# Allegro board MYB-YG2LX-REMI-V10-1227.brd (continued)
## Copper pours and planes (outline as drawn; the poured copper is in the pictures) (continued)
VDD_3V3 on BOTTOM: 26.31,48.72 26.31,47.8 25.8,47.29 24.61,47.29 24.46,47.45 24.46,48.26 24.51,48.31 25.14,48.31 25.22,48.39 25.22,48.87 25.35,49 26.03,49
VDD_3V3 on BOTTOM: 54.45,16.13 55.72,16.13 56.08,15.77 56.08,15.01 55.95,14.88 55.14,14.88 55.01,14.76 54.07,14.76 53.95,14.88 53.95,15.6 54.3,15.95 54.3,15.98
VDD_3V3 on ART04: 28.83,32.94 29.99,32.94 30.2,32.74 30.2,31.95 30.07,31.83 29.03,31.83 28.77,32.08 28.77,32.89
VDD_3V3 on ART04: 10.36,60.35 11.43,60.35 12.47,61.39 12.47,63.86 14.35,65.74 15.46,65.74 18.16,68.43 38.58,68.43 40.18,66.83 40.18,61.7 38.15,59.66 29.94,59.66 26.54,63.07 16.38,63.07 15.64,62.33 15.64,59.05 15.31,58.72 10.36,58.72 10.26,58.83 10.26,60.25
VDD_3V3 on POW05: 15.09,4.42 14.55,4.96 14.55,11.38 13.87,12.06 12.08,12.06 11.07,11.05 11.07,8.06 10.58,7.57 8.46,7.57 7.57,8.46 7.57,62.28 8.15,62.87 10.26,62.87 10.29,62.89 10.94,62.89 11.63,62.2 11.63,46.33 10.03,44.73 10.03,40.48 10.81,39.7 11.91,39.7 14.68,36.93 14.68,20.45 11.98,17.76 11.98,13.92 12.67,13.23 15.94,13.23 17.17,12.01 17.17,8.39 16.35,7.57 16.35,6.3 17.11,5.54 25.07,5.54 25.07,5.19 24.3,4.42
VDD_3V3 on POW05: 95.99,2.54 96.34,2.89 96.34,7.88 94.97,9.25 92.81,9.25 92.38,9.68 92.38,11.66 91.44,12.6 88.82,12.6 86.94,14.48 46.84,14.48 45.64,15.67 33.88,15.67 32.11,17.45 31.47,17.45 31.09,17.83 31.09,31.27 30.51,31.85 29.21,31.85 28.98,32.08 28.98,37.44 29.72,38.18 31.65,38.18 33.24,39.77 33.24,46.26 32.38,47.12 24.61,47.12 24.2,47.53 24.2,58.54 25.07,59.41 37.54,59.41 39.04,60.91 39.04,63.57 39.62,64.16 74.64,64.16 80.82,57.99 99.31,57.99 100.2,57.1 100.2,50.73 98.27,48.8 98.27,34.92 102.61,30.58 102.61,10.61 106.19,7.04 109.97,7.04 110,7.01 116.75,7.01 117.88,5.89 117.88,2.67 117.75,2.54
VDD_5V on TOP: 9.62,43.54 13.05,43.54 13.05,40.39 12.8,40.13 10.84,40.13 10.44,40.54 10.44,41.78 9.55,42.67 9.55,43.46
VDD_5V on TOP: 29.26,16.87 32.05,16.87 32.08,16.84 32.08,8.15 29.82,8.15 29.74,8.23 29.74,11.28 27.25,13.77 25.4,13.77 25.32,13.84 25.32,15.34 25.78,15.8 28.19,15.8
VDD_5V on TOP: 39.09,35.64 39.62,35.64 39.9,35.36 39.9,32.11 39.54,31.75 37.94,31.75 37.78,31.92 37.78,33.08 37.64,33.22 37.64,33.93 37.09,34.48 37.09,38.37 36.6,38.86 35.73,38.86 35.45,39.14 35.45,40.69 35.71,40.94 38.17,40.94 38.86,40.26 38.86,35.86
VDD_5V on TOP: 100.68,48.34 102.59,48.34 102.79,48.13 102.79,45.9 102.59,45.69 100.94,45.69 100.5,46.13 100.5,48.16
VDD_5V on TOP: 31.39,40.61 33.35,40.61 33.73,41 33.73,42.8 34.77,42.8 34.77,41.22 35.05,40.94 37,40.94 37.41,40.54 37.41,39.5 36.78,38.86 31.57,38.86 31.37,38.66 30.02,38.66 29.64,39.04 29.64,40.11 29.87,40.34 31.11,40.34
VDD_5V on TOP: 10.82,17.35 12.54,17.35 12.85,17.65 12.85,18.01 13.25,18.41 15.11,18.41 15.25,18.28 15.25,16.5 15.01,16.26 12.65,16.26 12.45,16.45 10.83,16.45 10.77,16.51 10.77,17.3
VDD_5V on TOP: 94.1,50.16 96.01,50.16 96.24,49.94 96.24,47.83 96.11,47.7 94.2,47.7 93.9,48.01 93.9,49.96
VDD_5V on TOP: 39.59,68.61 40.36,68.61 40.59,68.38 41.6,68.38 41.83,68.61 43.25,68.61 43.35,68.5 43.35,65.71 43.07,65.43 39.65,65.43 39.42,65.66 39.42,68.43
VDD_5V on BOTTOM: 76.27,14.66 77.01,14.66 77.36,14.3 77.36,11.56 77.03,11.23 77.01,11.23 77.01,10.06 77.09,9.98 77.09,8.66 77.01,8.59 76.2,8.59 76.02,8.76 76.02,14.4
VDD_5V on BOTTOM: 39.98,67.54 42.52,67.54 42.77,67.28 42.77,66.19 42.52,65.94 39.98,65.94 39.82,66.09 39.82,67.39
VDD_5V on BOTTOM: 102.59,48.34 102.79,48.13 102.79,45.9 102.59,45.69 100.91,45.69 100.9,45.71 100.03,45.71 99.64,46.1 99.64,47.73 100.25,48.34
VDD_5V on BOTTOM: 94.41,49.35 97.07,49.35 97.25,49.17 97.25,47.88 97.07,47.7 94.36,47.7 94.08,47.98 94.08,49.02
VDD_5V on BOTTOM: 40.28,5.97 39.7,6.55 30.04,6.55 29.8,6.8 29.8,11.17 30.15,11.52 41.03,11.52 43.3,9.25 48,9.25 49.39,10.63 53.65,10.63 54.1,10.19 54.1,8.84 54.35,8.59 56.64,8.59 57.63,7.59 57.63,5.49 57.15,5 53.01,5 52.04,5.97
VDD_5V on BOTTOM: 95.35,3.68 95.35,2.69 95.27,2.62 93.81,2.62 93.68,2.74 93.68,3.92 93.82,4.06 94.97,4.06
VDD_5V on BOTTOM: 44.19,58.32 44.19,56.59 43.28,55.68 39.32,55.68 38.32,56.67 38.32,57.48 36.06,59.74 31.75,59.74 31.44,60.05 21.23,60.05 20.25,59.07 16.21,59.07 15.92,59.36 15.92,62.99 15.95,63.02 15.95,66.88 18.16,69.09 37.26,69.09 38.81,67.54 38.81,61.54 40.26,60.1 43.96,60.1 44.4,59.66 44.4,58.52
VDD_5V on ART04: 16.53,62.66 25.65,62.66 26.49,61.82 26.49,59.44 25.24,58.19 25.24,49.76 22.95,47.46 22.95,44.13 21.61,42.8 19.68,42.8 14.54,37.66 14.54,24.18 16.75,21.97 22.37,21.97 26.73,17.61 28.41,17.61 28.83,17.2 32.64,17.2 32.64,14.53 32.03,13.92 32.03,9.53 31.87,9.37 29.94,9.37 29.84,9.47 29.84,10.9 28.67,12.06 26.06,12.06 25.88,11.89 14.17,11.89 13.97,12.09 11.73,12.09 11.53,11.89 8.33,11.89 8,12.22 8,49.33 8.91,50.24 17.62,50.24 20.54,53.16 20.54,57.76 19.38,58.93 15.92,58.93 15.92,62.05
VDD_5V on ART04: 93.14,2.62 97.68,2.62 105.08,10.01 105.08,42.16 105.41,42.49 105.41,46.13 103.27,48.26 101.7,48.26 100.83,49.12 95.78,49.12 95.17,48.51 95.17,47.35 96.31,46.2 101.77,46.2 102.99,44.98 102.99,12.17 95.37,4.55 93.04,4.55 93.04,2.72
VDD_5V on POW05: 87.43,2.54 86.71,3.25 86.71,6.94 84.94,8.71 70.79,8.71 70.77,8.74 69.66,8.74 69.64,8.71 29.84,8.71 29.75,8.8 29.75,10.93 28.62,12.06 26.58,12.06 25.07,10.55 25.07,6.05 17.32,6.05 16.86,6.51 16.86,7.36 17.67,8.18 17.67,12.22 16.15,13.74 12.88,13.74 12.49,14.13 12.49,17.55 15.19,20.24 15.19,37.14 12.12,40.21 11.02,40.21 10.54,40.69 10.54,44.52 12.14,46.12 12.14,62.41 11.15,63.4 10.8,63.4 12.14,64.74 12.14,66.27 14.3,68.43 29.1,68.43 29.66,68.99 38.93,68.99 39.49,68.43 42.44,68.43 42.44,64.8 42.31,64.67 39.41,64.67 38.53,63.78 38.53,61.12 37.33,59.92 24.86,59.92 23.69,58.75 23.69,47.32 24.4,46.61 32.17,46.61 32.74,46.05 32.74,39.98 31.44,38.68 29.51,38.68 28.47,37.65 28.47,31.87 29,31.34 30.29,31.34 30.58,31.06 30.58,17.62 31.26,16.94 31.9,16.94 33.67,15.16 45.43,15.16 46.63,13.97 86.73,13.97 88.61,12.09 91.23,12.09 91.87,11.45 91.87,9.47 92.6,8.74 94.76,8.74 95.83,7.67 95.83,3.1 95.27,2.54
VDD_5V_VBUS on TOP: 105.05,52.58 113.23,52.58 113.64,52.17 113.64,50.88 108.66,50.88 106.98,49.2 106.98,46.58 106.9,46.51 104.9,46.51 104.75,46.66 104.75,52.27
VDD_5V_VBUS on BOTTOM: 104.82,52.58 113.36,52.58 113.94,51.99 113.94,51.05 113.76,50.88 108.66,50.88 108.33,50.55 108.3,50.55 107.01,49.25 107.01,46.51 106.8,46.3 105.33,46.3 104.8,46.84 104.8,52.55
VDD_5V_VBUS on ART04: 94.66,52.6 113.41,52.6 113.69,52.32 113.69,50.88 108.43,50.88 107.9,50.34 107.87,50.34 106.93,49.4 106.93,48.87 106.8,48.74 101.8,48.74 101.44,49.1 101.42,49.1 100.96,49.56 94.89,49.56 94.31,50.14 94.31,52.25
VDD_BAT on BOTTOM: 69.8,65.43 70.86,65.43 70.94,65.35 70.94,63.64 70.81,63.51 69.78,63.51 69.59,63.7 69.59,65.23
VDD_BL_3V3 on BOTTOM: 26.79,49.05 27.78,49.05 28.6,48.23 28.6,46.02 28.83,45.8 28.83,44.73 28.11,44.02 25.8,44.02 25.49,44.34 25.49,45.12 25.95,45.59 26.64,45.59 26.74,45.69 26.74,49
VDD_BL_3V3 on ART04: 29.13,53.42 29.63,52.92 29.63,41.97 28.49,40.84 25.6,40.84 25.14,40.39 25.14,38.66 24.86,38.38 19.63,38.38 19.05,38.96 19.05,41.66 19.88,42.49 21.92,42.49 23.26,43.84 23.26,47.35 25.57,49.66 25.57,53.31 25.68,53.42
VDD_LDO on TOP: 67.66,10.69 70.94,10.69 71.01,10.62 71.01,10.13 70.99,10.11 69.11,10.11 68.96,10.26 68.09,10.26 67.94,10.11 67.59,10.11 67.59,10.62
VDD_LDO on TOP: 71.09,11.79 67.76,11.79 67.71,11.84 67.71,12.47 68.3,13.06 71.22,13.06 71.29,12.98 71.29,11.99
VDD_PHY0_3V3 on TOP: 101.22,22.66 102.87,22.66 103.12,22.4 103.12,21.56 102.76,21.21 101.24,21.21 101.09,21.36 101.09,22.53
VDD_PHY0_3V3 on TOP: 90.29,18.14 92.12,18.14 92.2,18.06 92.2,17.55 92.12,17.48 90.27,17.48 90.24,17.5 90.24,18.08
VDD_PHY0_3V3 on BOTTOM: 101.24,22.63 102.46,22.63 102.64,22.45 102.64,21.36 102.51,21.23 101.24,21.23 101.11,21.36 101.11,22.5
VDD_PHY0_3V3 on BOTTOM: 90.39,18.59 91.92,18.59 92.05,18.47 92.05,17.17 91.99,17.12 90.85,17.12 90.27,17.7 90.27,18.47
VDD_PHY0_3V3 on ART04: 96.74,24.79 96.74,26.72 97.51,27.48 102.18,27.48 102.64,27.03 102.64,21.55 102.18,21.09 100.69,21.09 100.35,21.44 100.35,22.96 99.74,23.57 99.74,24.82 99.49,25.07 98.4,25.07 97.82,24.5 97.82,22.64 94.42,19.24 94.43,19.23 94.43,17.63 94.1,17.3 90.37,17.3 90.14,17.53 90.14,18.24 90.37,18.47 91.36,18.47 91.97,19.08 91.97,22.76 94,24.79
VDD_PHY1_3V3 on TOP: 91.16,37.69 92.07,37.69 92.15,37.62 92.15,37.13 92.1,37.08 90.27,37.08 90.24,37.11 90.24,37.64 90.34,37.74 91.11,37.74
VDD_PHY1_3V3 on TOP: 95.75,29.18 97.33,29.18 97.61,28.91 97.61,27.33 97.38,27.1 95.7,27.1 95.53,27.28 95.53,28.96
VDD_PHY1_3V3 on BOTTOM: 91.18,37.57 91.18,37.36 91.39,37.16 91.79,37.16 91.92,37.03 91.92,36.55 91.84,36.47 91.33,36.47 90.75,37.06 90.34,37.06 90.29,37.11 90.29,37.54 90.47,37.72 91.03,37.72
VDD_PHY1_3V3 on ART04: 91.79,37.87 92.78,37.87 92.86,37.8 92.86,37.31 92.63,37.08 90.29,37.08 90.22,37.16 90.22,37.59 90.34,37.72 91.64,37.72
VDD_RGMII0 on BOTTOM: 92.07,19.91 92.68,20.52 93.37,20.52 93.47,20.42 93.47,19.28 93.19,19 92.33,19 92.22,18.9 89.66,18.9 89.56,19 89.56,19.76 89.71,19.91
VDD_RGMII0 on ART04: 89.58,28.7 91.13,27.15 91.13,19.43 90.57,18.87 89.45,18.87 87.66,20.66 86.78,20.66 86.28,21.16 86.28,28.45 86.53,28.7
VDD_RGMII1 on BOTTOM: 90.62,38.38 91.26,38.38 91.61,38.02 93.06,38.02 93.25,37.83 93.25,36.25 93.51,35.99 93.51,33.85 93.16,33.5 90.55,33.5 90.45,33.6 90.45,34.54 90.65,34.75 92.2,34.75 92.35,34.9 92.35,37.13 92.15,37.34 91.56,37.34 91.28,37.62 91.28,37.77 91.18,37.87 90.6,37.87 90.52,37.95 90.52,38.28
VDD_RGMII1 on ART04: 88.77,44.63 88.13,43.99 85.34,43.99 84.22,42.88 84.22,40.59 84.55,40.26 91.23,40.26 91.84,39.65 91.84,38.4 91.46,38.02 90.6,38.02 90.5,38.13 90.5,38.3 90.27,38.53 89.51,38.53 89.02,38.05 89.02,37.44 89.66,36.8 91.51,36.8 91.84,36.47 91.84,33.58 91.39,33.12 83.82,33.12 83.44,33.5 83.44,49.48 83.87,49.91 88.21,49.91 88.77,49.35
VDD_RTC on BOTTOM: 73.1,67.16 76.6,67.16 76.83,66.93 76.83,66.27 76.58,66.01 74.82,66.01 74.52,65.71 74.52,64.69 73.94,64.11 73.12,64.11 72.89,64.34 72.89,66.95
VDD_RTC on BOTTOM: 68.22,67.39 68.93,67.39 69.16,67.16 69.16,63.25 68.96,63.04 67.71,63.04 67.71,66.88
VDD_RTC on ART04: 69.11,69.34 73.88,69.34 74.75,68.48 74.75,64.9 74.19,64.34 67.2,64.34 67.1,64.44 67.1,67.34
VDD_SD on TOP: 7.84,61.49 8.58,61.49 8.81,61.26 8.81,59.44 8.73,59.36 7.59,59.36 7.59,61.24
VDD_SD on BOTTOM: 8.86,61.98 8.86,59.16 8.71,59 7.59,59 7.46,59.13 7.46,62.03 7.59,62.15 8.68,62.15
VDD_SD on ART04: 7.77,61.47 9.52,61.47 9.85,61.14 9.85,57.53 9.95,57.43 18.51,57.43 19,57.91 19.48,57.91 19.88,57.51 19.88,53.9 16.76,50.77 14.68,50.77 14.32,51.13 14.32,51.38 13.71,51.99 13.15,51.99 13,51.84 13,51.08 12.8,50.88 12.09,50.88 11.4,51.56 7.59,51.56 7.57,51.59 7.57,61.26
VDD_SOM_3V3OUT on TOP: 11.02,62.08 11.02,60.78 10.94,60.71 9.32,60.71 9.22,60.81 9.22,62.13 9.32,62.23 10.87,62.23
VDD_SOM_3V3OUT on ART03: 11.17,62.08 11.22,62.03 11.22,60.71 11.12,60.6 9.29,60.6 9.06,60.83 9.06,61.8 9.34,62.08
VDD_SOM_3V3OUT on ART04: 10.08,62.23 11.15,62.23 11.25,62.13 11.25,60.88 11.07,60.71 10.38,60.71 9.95,61.14 9.95,62.1
VDD_SOM_5VIN on TOP: 47.14,50.9 43.96,50.9 43.95,50.91 43.7,50.91 43.53,51.08 43.53,53.31 43.76,53.54 47.14,53.54 47.47,53.21 47.47,51.23
VDD_SOM_5VIN on BOTTOM: 47.32,51.21 47.32,54.03 47.04,54.31 47.04,57.89 46.76,58.17 45.08,58.17 44.98,58.06 44.98,55.83 44.62,55.47 44.19,55.47 44.08,55.36 44.08,53.86 43.56,53.34 43.56,51.05 43.68,50.93 47.04,50.93
VDD_USB0_VBUS on TOP: 86.94,8.56 89.53,8.56 90.55,7.54 90.55,5.69 90.42,5.56 87.73,5.56 86.76,4.6 86.76,3.38 86.48,3.1 83.97,3.1 83.66,2.79 81.78,2.79 81.76,2.82 81.76,4.11 81.96,4.11 82.06,4.22 82.06,4.5 84.71,4.5 86.58,6.38 86.58,8.2
VDD_USB0_VBUS on TOP: 79.02,7.65 79.27,7.65 79.35,7.57 79.35,6.12 79.4,6.07 81.1,6.07 81.4,6.38 81.4,7.59 81.45,7.65 81.83,7.65 81.83,6.25 81.58,5.99 81.58,5.08 82.14,4.52 82.14,2.79 78.48,2.79 78.1,3.17 78.1,4.5 78.63,5.03 78.63,6.12 78.89,6.38 78.89,7.52
VDD_USB0_VBUS on BOTTOM: 78.13,2.31 77.87,2.57 77.87,3.91 78.13,4.17 78.13,4.45 78.38,4.7 78.66,4.7 78.71,4.65 78.71,3.61 79.22,3.1 80.01,3.1 80.69,3.78 81.3,3.78 81.5,3.99 81.5,4.62 81.58,4.7 84.88,4.7 85.39,5.21 85.39,6.6 86.61,7.82 86.61,9.6 86.89,9.88 88.95,9.88 89.05,9.78 89.05,9.07 89.11,9 90.23,9 91.06,9.83 92.05,9.83 92.05,8.33 90.14,6.43 87.87,6.43 87.59,6.15 87.59,3.77 86.56,2.74 83.97,2.74 83.54,2.31
VDD_VBUS on TOP: 63.06,9.07 63.65,9.07 63.85,8.86 63.85,6.91 64.41,6.35 64.41,6.17 64.36,6.12 64,6.12 63.22,6.91 63.22,8 62.96,8.26 62.96,8.97
VDD_VBUS on TOP: 59.84,4.75 58.01,4.75 57.73,5.03 51.91,5.03 51.2,5.74 51.2,8.18 51.61,8.59 56.79,8.59 57.91,7.47 59.84,7.47
VDD_VBUS on TOP: 64.88,6.74 65.1,6.53 66.77,6.53 66.98,6.73 67.61,6.73 67.89,7.01 67.89,8.1 67.79,8.2 67.79,9.19 68.04,9.45 68.04,10.01 68.09,10.06 68.8,10.06 68.98,9.88 68.98,8.28 68.78,8.08 68.78,3.35 68.27,2.84 63.72,2.84 62.48,4.09 60.63,4.09 59.97,4.75 58.09,4.75 57.93,4.9 57.93,7.47 62.35,7.47 62.91,8.03 62.91,8.99 63.85,8.99 63.98,8.86 63.98,8.28 64,8.26 64,6.86 64.12,6.74
VDD_VBUS on TOP: 68.7,9.07 68.12,9.07 67.91,8.86 67.91,6.91 67.35,6.35 67.35,6.17 67.41,6.12 67.76,6.12 68.55,6.91 68.55,8 68.8,8.26 68.8,8.97
VDD_VBUS on BOTTOM: 60.6,4.11 60.07,4.65 58.19,4.65 57.93,4.9 57.93,7.87 59,8.94 59.79,8.94 60.04,9.19 60.91,9.19 61.16,8.94 62.76,8.94 62.81,8.99 64.41,8.99 64.87,8.53 64.87,6.76 65.1,6.53 66.77,6.53 66.9,6.65 66.9,8.64 67.23,8.97 67.51,8.97 67.51,9.07 67.79,9.35 67.79,11 67.53,11.25 66.93,11.25 66.87,11.3 66.87,11.58 66.98,11.68 68.02,11.68 68.06,11.65 68.64,11.65 68.65,11.63 69.72,11.63 70.23,11.13 70.23,9.47 69.13,8.38 69.13,4.7 67.26,2.82 63.72,2.82 62.43,4.11
VDD_VBUS on ART03: 57.76,4.8 57.35,5.21 57.35,6.99 57.81,7.44 58.59,7.44 59.1,7.95 59.1,10.79 59.41,11.1 66.32,11.1 67.28,10.13 68.86,10.13 69.16,9.83 69.16,9.07 68.78,8.69 68.78,7.26 68.09,6.58 68.09,5.64 67.97,5.51 66.06,5.51 64.61,4.06 58.52,4.06 57.78,4.8
VDD_VBUS_5V on TOP: 57.65,2.57 55.9,2.57 55.9,2.54 55.5,2.13 55.5,0.69 55.44,0.64 53.79,0.64 53.46,0.97 53.46,4.52 53.62,4.67 57.4,4.67 57.65,4.42
VDD_VBUS_5V on BOTTOM: 54.86,4.24 58.06,4.24 58.14,4.17 58.14,1.96 58.11,1.93 54.71,1.93 54.61,2.03 54.61,3.99
VDD_VBUS_5V on ART04: 33.93,18.59 33.85,18.52 31.21,18.52 30.83,18.9 30.83,21.74 31.11,22.02 33.57,22.02 33.93,21.67
VDD_VBUS_5V on ART04: 54.4,4.55 57.25,4.55 57.7,4.09 57.7,3.2 57.53,3.02 54.66,3.02 54.4,3.28
VDDA_AUDIO_3V3 on BOTTOM: 38.15,18.41 41.7,18.41 41.7,16.79 41.63,16.71 38.17,16.71 38.02,16.87 38.02,18.29
VDDA_PHY0_1V1 on BOTTOM: 99.21,24.99 99.31,24.89 99.31,24.23 99.26,24.18 97.18,24.18 97.13,24.23 97.13,24.79 97.33,24.99
VDDA_PHY0_1V1 on ART04: 98.32,24.77 99.28,24.77 99.56,24.49 99.56,21.79 99.06,21.29 98.47,21.29 98.19,21.56 98.19,24.64
VDDA_PHY0_3V3 on TOP: 100.43,13.89 101.55,13.89 101.57,13.87 101.57,12.57 101.44,12.45 100.53,12.45 100.33,12.65 100.33,13.79
VDDA_PHY1_1V1 on BOTTOM: 99.31,42.52 100.5,42.52 100.55,42.47 100.55,41.78 100.4,41.63 100.4,41.27 100.17,41.05 99.31,41.05 99.16,41.2 99.16,42.37
VDDA_PHY1_3V3 on TOP: 100.91,33.48 102.03,33.48 102.1,33.4 102.1,32.11 101.98,31.98 100.96,31.98 100.76,32.18 100.76,33.32
VDDL_PHY0_1V1 on BOTTOM: 86.84,15.06 89.63,15.06 90.04,14.66 90.93,14.66 91.06,14.53 91.06,14.22 90.95,14.12 89.35,14.12 88.87,13.64 88.87,12.42 86.84,12.42
VDDL_PHY0_1V1 on BOTTOM: 96.01,25.98 96.41,25.98 96.82,25.58 96.82,23.77 96.72,23.67 95.96,23.67 95.86,23.77 95.86,25.83
VDDL_PHY0_1V1 on ART04: 92.6,26.92 96.16,26.92 96.44,26.64 96.44,25.17 96.36,25.1 95.88,25.1 95.42,25.55 93.72,25.55 93.01,24.84 93.01,24.43 92.91,24.33 92.43,24.33 92.17,24.59 92.17,26.49
VDDL_PHY1_1V1 on TOP: 99.97,44.42 100.94,44.42 100.99,44.37 100.99,42.75 100.91,42.67 100.2,42.67 100.12,42.75 100.12,43.54 99.89,43.76 99.89,44.35
VDDL_PHY1_1V1 on BOTTOM: 100.07,44.48 100.71,44.48 101.01,44.17 101.01,42.93 100.91,42.82 99.89,42.82 99.77,42.95 99.77,44.17
VDDL_PHY1_1V1 on BOTTOM: 84.96,35.31 84.83,35.18 83.99,35.18 83.89,35.28 83.89,41.43 84.02,41.55 85.29,41.55 85.39,41.45 85.39,40.64 84.96,40.21
VDDL_PHY1_1V1 on ART04: 89.04,43.7 91.23,45.9 100.35,45.9 100.83,45.42 100.83,43.89 100.76,43.81 99.77,43.81 99.61,43.97 98.47,43.97 97.74,43.23 95.25,43.23 94.97,42.95 94.97,40.92 94.53,40.49 84.71,40.49 84.53,40.67 84.53,42.75 85.48,43.7
AUDIO_AGND on BOTTOM: 38.32,12.32 37.54,13.11 35.45,13.11 35.2,13.36 35.2,14.58 35.43,14.81 37.51,14.81 38.05,15.34 38.05,16.26 38.15,16.36 42.11,16.36 42.41,16.66 42.41,22.15 41.65,22.91 41.65,24.82 41.68,24.84 43.68,24.84 43.99,24.54 43.99,12.9 43.4,12.32
LT8912_VCCA_HDMIPLL on BOTTOM: 16.23,28.27 16.3,28.19 16.3,25.81 15.92,25.43 14.47,25.43 14.47,26.24 14.3,26.42 14.3,28.19 14.37,28.27
LT8912_VCCA_HDMIPLL on BOTTOM: 19.96,21.56 19.96,20.7 19.88,20.62 19,20.62 18.74,20.37 18.74,19.81 18.67,19.74 17.37,19.74 17.04,20.07 14.73,20.07 14.47,20.32 14.47,26.06 16.3,26.06 16.3,22 16.46,21.84 19.68,21.84
LT8912_VCCA_HDMITX on BOTTOM: 26.51,24.74 27.12,24.13 27.12,21.49 26.74,21.11 24.18,21.11 24.02,21.26 24.02,22.02 24.23,22.23 24.81,22.23 24.94,22.35 24.94,23.27 25.04,23.37 25.27,23.37 25.35,23.44 25.35,24.61 25.47,24.74
N23725979 on BOTTOM: 9.55,45.72 11.2,45.72 11.45,45.47 11.45,41.81 11.3,41.66 10.36,41.66 10.23,41.78 10.23,43 10,43.23 9.62,43.23 9.34,43.51 9.34,45.52
N24697239 on TOP: 92.17,17.17 92.17,17.07 92.1,16.99 91.54,16.99 90.93,16.38 90.19,16.38 90.17,16.41 90.17,17.02 90.39,17.25 92.1,17.25
N24697239 on BOTTOM: 87.93,17.3 90.19,17.3 90.67,16.81 91,16.81 91,16.38 90.93,16.31 89.99,16.31 89.76,16.08 87.93,16.08 87.78,16.23 87.78,17.14
N24806599 on TOP: 92.17,36.81 92.17,36.7 92.1,36.63 91.54,36.63 90.88,35.97 90.24,35.97 90.17,36.65 90.39,36.88 92.1,36.88
N24806599 on BOTTOM: 90.67,36.73 91.08,36.32 91.08,36.17 90.88,35.97 90.22,35.97 89.96,35.71 89.96,35.23 89.91,35.18 86.15,35.18 85.95,35.38 85.95,37.06 86.1,37.21 88.77,37.21 89.25,36.73
N25530830 on BOTTOM: 55.04,14.55 57.48,14.55 57.7,14.33 57.7,13.97 57.88,13.79 58.9,13.79 59.05,13.64 59.05,11.76 58.72,11.43 57.96,11.43 57.73,11.66 57.73,12.9 57.53,13.11 57.53,13.13 55.09,13.13 54.99,13.23 54.99,14.5
N25531113 on BOTTOM: 48.22,13.78 48.41,13.97 48.41,14.55 49.07,14.55 49.15,14.48 49.15,14.05 49.27,13.92 50.44,13.92 50.9,13.46 50.9,11.71 50.69,11.51 49.91,11.51 49.58,11.84 49.58,12.83 49.25,13.16 48.38,13.16 48.28,13.06 47.09,13.06 46.99,13.16 46.99,13.67 47.1,13.78
N25776699 on BOTTOM: 8.73,45.77 9.06,45.44 9.06,41.81 8.76,41.5 7.59,41.5 7.59,45.59 7.77,45.77
N26033282 on TOP: 39.72,45.11 41.6,45.11 41.96,44.75 41.96,42.11 41.3,41.45 35.12,41.45 35.07,41.5 35.07,42.93 35.28,43.13 38.71,43.13 39.42,43.84 39.42,44.81
N26043137 on TOP: 39.11,28.88 38.91,29.08 38.91,30.28 39.11,30.48 42.95,30.48 43.15,30.28 43.15,29.06 42.97,28.88
N26045371 on BOTTOM: 21.81,50.52 23.01,50.52 23.29,50.8 24.28,50.8 24.48,50.6 24.48,49.94 23.92,49.38 23.34,49.38 22.68,48.72 22.68,46.56 22.42,46.3 21.94,46.3 21.84,46.41 21.84,48.97 21.66,49.15 21.66,50.37
N26059117 on BOTTOM: 96.26,7.85 99.21,7.85 99.64,7.42 99.64,6.93 99.46,6.76 97.76,6.76 97.13,6.12 97.13,4.52 96.86,4.25 96.2,4.25 95.73,4.72 95.73,7.32
N26059441 on BOTTOM: 94.51,7.87 95.32,7.87 95.42,7.77 95.42,4.67 96.21,3.89 97.51,3.89 97.76,4.14 97.76,4.9 98.93,6.07 99.54,6.07 99.79,5.82 99.79,5.18 98.98,4.37 98.98,2.95 98.34,2.31 95.91,2.31 95.63,2.59 95.63,3.91 94.56,4.98 94.46,4.98 94.46,7.82
N26059598 on BOTTOM: 96.24,9.88 96.63,9.49 96.63,8.62 96.34,8.33 92.81,8.33 92.68,8.46 92.68,9.58 92.99,9.88
N26081452 on TOP: 32.08,32.49 33.12,32.49 33.35,32.26 33.35,30.18 33.75,29.77 35.45,29.77 35.76,29.46 35.76,29.01 35.2,28.45 32.13,28.45 32.13,29.49 31.75,29.87 31.75,31.17 32.08,31.5
N26137432 on TOP: 97.76,52.43 98.04,52.43 98.13,52.34 98.13,51.5 98.47,51.16 99.72,51.16 99.82,51.05 99.82,50.14 99.72,50.04 98.83,50.04 97.86,49.07 97.07,49.07 96.74,49.4 96.74,50.55 97.61,51.41 97.61,51.64 97.68,51.71 97.68,52.35
N26137432 on BOTTOM: 98.32,51.21 99.77,51.21 99.82,51.16 99.82,50.14 99.69,50.01 98.4,50.01 98.29,50.11 98.29,51.18

Small or netless copper shapes (teardrops, artwork), in the pictures only: 1 on TOP

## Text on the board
Ref Des/Silkscreen Bottom: J5 | eMMC | Download | Boot Device | 0 | S0 | S1 | 1 | S2 | Micro SD
User.Comments: CR_1_1 | CR_3_1
Board Geometry/Outline: ROUT
Board Geometry/Soldermask Top: Remi Pi
Ref Des/Silkscreen Top: J6 | J2 | M33 Debug | U11 | J7 | U7 | A55 Debug | U22 | Y4 | U3 | U24 | U15 | U4 | J8 | L2 | OFF/ON | U1 | U26 | J13 | J1 | J3 | J14 | S0 | S2 | S1 | ON | Y7 | 1 | U16 | SW1 | U10 | 0 | OFF | J4 | J9 | J10 | MIPI CSI | LVDS | Reset | User | USB HOST | ENET0 | ENET1 | HDMI | WL ANT | WL/BT ANT | AUDIO | VBUS_5V | USB type-c | MYB-YG2LX-REMI_V10
DIMENSION: 100 ohm | 90 ohm | 50 ohm | 1,6 | 1 | 3 | 17.0 | + | - | 5 | L2&L5 | L3 | L2 | MYB-YG2LX_V01 | 2022-10-27
User.14: FIGURE | SIZE | 8.0 | 19.69 | 23.62 | 35.43 | 36.22 | 86.61 | 125.0 | 125.98 | 127.95 | 25.59 | 39.37 | 66.93 | 70.87 | 118.11 | 47.24x23.62 | 59.06x27.56 | 62.99x23.62 | 62.99x39.37 | 70.87x23.62 | 70.87x27.56 | 82.68x39.37 | 106.3x39.37 | DRILL CHART: TOP to BOTTOM | ALL UNITS ARE IN MILS | TOLERANCE | +3.0/-3.0 | +0.0/-0.0 | PLATED | NON-PLATED | QTY | 1472 | 32 | 1 | 40 | 8 | 4 | 2
